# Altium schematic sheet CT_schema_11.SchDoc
size 147 x 119 mm
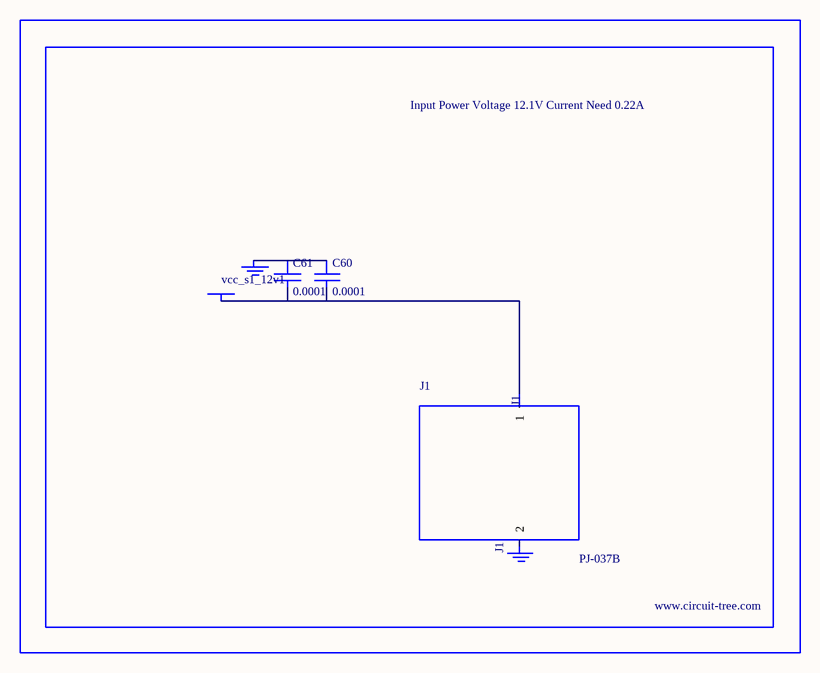
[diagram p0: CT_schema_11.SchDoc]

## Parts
BORDER10  (no value)
C60  0.0001  [EXV-9H]
C61  0.0001  [EXV-9H]
GND_INSTANCE_10_0  (no value)
GND_INSTANCE_10_1  (no value)
J1  PJ-037B  [PJ-037B_PACKAGE]
POWER_INSTANCE_10_0  vcc_s1_12v1

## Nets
NetC60_1: C60.1 C61.1 GND_INSTANCE_10_0.0(GND)
NetC60_2: C60.2 C61.2 J1.1 POWER_INSTANCE_10_0.0(PWR)

Not connected (* = marked no-connect by the designer): GND_INSTANCE_10_1 0(GND); J1 2

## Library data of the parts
BORDER10 = BORDER_PAGE10
C60 C61 = EDK107M035A9HAA
GND_INSTANCE_10_0 GND_INSTANCE_10_1 = GND
POWER_INSTANCE_10_0 = PWR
